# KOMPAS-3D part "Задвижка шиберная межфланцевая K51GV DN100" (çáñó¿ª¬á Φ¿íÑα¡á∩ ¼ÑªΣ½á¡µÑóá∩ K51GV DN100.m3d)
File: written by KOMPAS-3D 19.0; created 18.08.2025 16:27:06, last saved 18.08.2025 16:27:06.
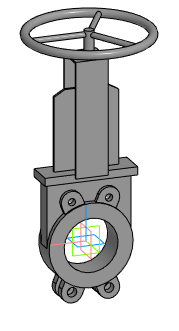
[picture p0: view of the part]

Document properties: Автор: Евгений; Полное имя файла: E:\Dendor Работа Сачек\3D для проектировщиков\2.4 Тип K51GV. Задвижка шиберная межфланцевая\stp_Задвижка шиберная K51GV DN50-400 с маховиком\Задвижка шиберная межфланцевая K51GV DN100.m3d

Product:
- Part/product: Задвижка шиберная межфланцевая K51GV DN100

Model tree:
1. Операция без истории:1  (labels: Задвижка шиберная межфланцевая K51GV DN100)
